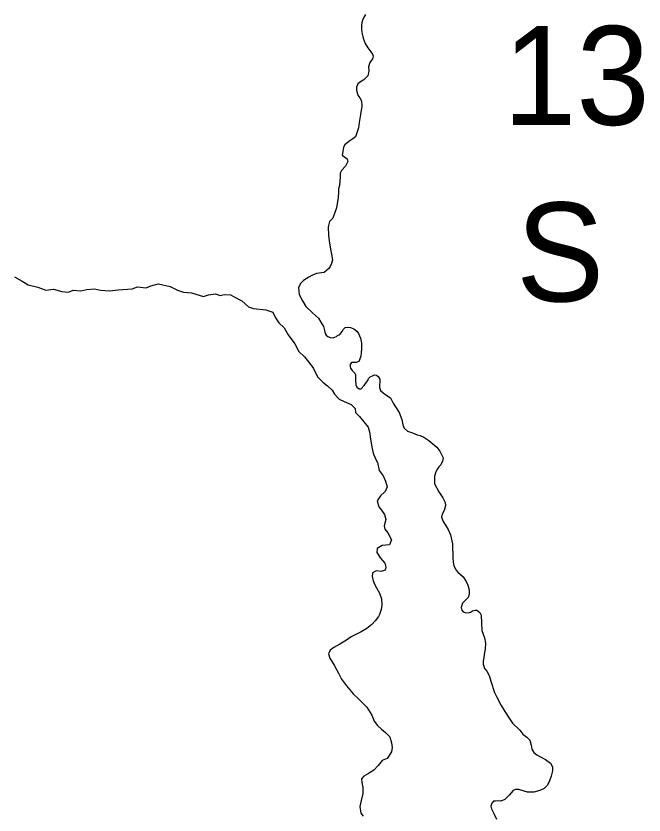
# Model space of a CAD drawing. Extents: x -492261 to -432772, y 1441225 to 1452922.
# Drawn here: x -459293.9 to -459176.4, y 1452357.2 to 1452506.5 of the extents above; entities that cross this region are included whole.
import ezdxf

# ---------------------------------------------------------------- set-up
doc = ezdxf.new("R2010")
doc.units = 0
doc.layers.add('Default', color=7, linetype='Continuous')

msp = doc.modelspace()

# ---------------------------------------------------------------- linework, layer by layer
at = {"layer": 'Default'}
for points in [[(-459228.54, 1452506.83), (-459228.89, 1452506.18), (-459229.12, 1452505.58), (-459229.26, 1452504.85), (-459229.26, 1452503.95), (-459229.14, 1452503.17), (-459228.99, 1452502.4), (-459228.56, 1452501.4), (-459228.11, 1452500.57), (-459227.51, 1452499.85), (-459227.23, 1452499.42), (-459227.08, 1452499.02), (-459227.23, 1452498.49), (-459227.71, 1452497.82), (-459227.98, 1452497.04), (-459227.9, 1452496.21), (-459228.1, 1452495.36), (-459228.87, 1452494.59), (-459229.47, 1452494.23), (-459229.94, 1452493.86), (-459230.24, 1452493.21), (-459230.22, 1452492.66), (-459229.99, 1452491.75), (-459229.59, 1452491.2), (-459229.29, 1452490.65), (-459229.21, 1452489.7), (-459229.46, 1452488.12)], [(-459228.54, 1452506.83), (-459228.89, 1452506.18), (-459229.12, 1452505.58), (-459229.26, 1452504.85), (-459229.26, 1452503.95), (-459229.14, 1452503.17), (-459228.99, 1452502.4), (-459228.56, 1452501.4), (-459228.11, 1452500.57), (-459227.51, 1452499.85), (-459227.23, 1452499.42), (-459227.08, 1452499.02), (-459227.23, 1452498.49), (-459227.71, 1452497.82), (-459227.98, 1452497.04), (-459227.9, 1452496.21), (-459228.1, 1452495.36), (-459228.87, 1452494.59), (-459229.47, 1452494.23), (-459229.94, 1452493.86), (-459230.24, 1452493.21), (-459230.22, 1452492.66), (-459229.99, 1452491.75), (-459229.59, 1452491.2), (-459229.29, 1452490.65), (-459229.21, 1452489.7), (-459229.46, 1452488.12)], [(-459229.46, 1452488.12), (-459229.71, 1452486.62), (-459229.83, 1452485.64), (-459230.08, 1452484.89), (-459230.4, 1452483.94), (-459230.87, 1452483.54), (-459231.62, 1452483.06), (-459232.37, 1452482.44), (-459232.62, 1452482.01), (-459232.69, 1452481.58), (-459232.86, 1452480.51), (-459231.94, 1452479.83), (-459231.81, 1452479.31), (-459232.24, 1452478.45), (-459233.03, 1452477.65), (-459233.26, 1452477.15), (-459233.26, 1452476.43), (-459233.38, 1452474.82), (-459233.58, 1452474.22), (-459233.6, 1452473.65), (-459233.65, 1452472.62), (-459233.97, 1452470.66), (-459234.66, 1452468.76), (-459235.24, 1452468.11), (-459235.51, 1452467.13), (-459235.43, 1452465.53), (-459235.26, 1452464.05), (-459235, 1452462.63), (-459234.88, 1452462.02), (-459234.7, 1452460.95), (-459234.87, 1452460.25), (-459235.12, 1452459.72), (-459235.4, 1452459.34), (-459236.24, 1452458.59), (-459237.71, 1452458.39), (-459238.59, 1452458.04), (-459239.14, 1452457.74), (-459240.13, 1452457.11), (-459240.7, 1452456.51), (-459241.08, 1452455.73), (-459240.95, 1452454.45), (-459240.28, 1452453.3), (-459239.67, 1452452.23), (-459238.45, 1452451.03), (-459237.3, 1452450.03), (-459236.85, 1452449.33), (-459236.38, 1452448.5), (-459236.17, 1452447.75), (-459236.07, 1452447.2), (-459235.87, 1452446.85), (-459235.55, 1452446.62), (-459235.12, 1452446.45), (-459234.6, 1452446.35), (-459233.98, 1452446.65), (-459233.75, 1452446.8), (-459233.3, 1452447), (-459232.91, 1452447.58), (-459232.63, 1452448), (-459232.36, 1452448.28), (-459231.84, 1452448.38), (-459231.34, 1452448.31), (-459230.71, 1452448.06), (-459230.14, 1452447.61), (-459229.81, 1452447.21), (-459229.49, 1452446.31), (-459229.29, 1452445.35), (-459229.28, 1452444.4), (-459229.33, 1452443.6), (-459229.43, 1452442.93), (-459229.63, 1452442.27), (-459229.8, 1452441.92), (-459230.28, 1452441.75), (-459230.68, 1452441.75), (-459231.15, 1452441.75), (-459231.37, 1452441.4), (-459231.4, 1452441.04), (-459231.32, 1452440.72), (-459231, 1452440.27), (-459230.7, 1452439.97), (-459230.5, 1452439.74), (-459230.4, 1452439.47), (-459230.37, 1452439.17), (-459230.37, 1452438.34), (-459230.35, 1452437.79), (-459230.34, 1452437.57), (-459230.17, 1452437.14), (-459229.72, 1452436.87), (-459229.32, 1452436.87), (-459228.75, 1452437.44), (-459228.35, 1452438.09), (-459228.1, 1452438.42), (-459227.95, 1452438.77), (-459227.63, 1452439.1), (-459227.08, 1452439.35), (-459226.86, 1452439.45), (-459226.48, 1452439.4), (-459226.13, 1452439.15), (-459225.83, 1452438.67), (-459225.86, 1452438.05), (-459225.88, 1452437.65), (-459225.9, 1452437.1)], [(-459229.46, 1452488.12), (-459229.71, 1452486.62), (-459229.83, 1452485.64), (-459230.08, 1452484.89), (-459230.4, 1452483.94), (-459230.87, 1452483.54), (-459231.62, 1452483.06), (-459232.37, 1452482.44), (-459232.62, 1452482.01), (-459232.69, 1452481.58), (-459232.86, 1452480.51), (-459231.94, 1452479.83), (-459231.81, 1452479.31), (-459232.24, 1452478.45), (-459233.03, 1452477.65), (-459233.26, 1452477.15), (-459233.26, 1452476.43), (-459233.38, 1452474.82), (-459233.58, 1452474.22), (-459233.6, 1452473.65), (-459233.65, 1452472.62), (-459233.97, 1452470.66), (-459234.66, 1452468.76), (-459235.24, 1452468.11), (-459235.51, 1452467.13), (-459235.43, 1452465.53), (-459235.26, 1452464.05), (-459235, 1452462.63), (-459234.88, 1452462.02), (-459234.7, 1452460.95), (-459234.87, 1452460.25), (-459235.12, 1452459.72), (-459235.4, 1452459.34), (-459236.24, 1452458.59), (-459237.71, 1452458.39), (-459238.59, 1452458.04), (-459239.14, 1452457.74), (-459240.13, 1452457.11), (-459240.7, 1452456.51), (-459241.08, 1452455.73), (-459240.95, 1452454.45), (-459240.28, 1452453.3), (-459239.67, 1452452.23), (-459238.45, 1452451.03), (-459237.3, 1452450.03), (-459236.85, 1452449.33), (-459236.38, 1452448.5), (-459236.17, 1452447.75), (-459236.07, 1452447.2), (-459235.87, 1452446.85), (-459235.55, 1452446.62), (-459235.12, 1452446.45), (-459234.6, 1452446.35), (-459233.98, 1452446.65), (-459233.75, 1452446.8), (-459233.3, 1452447), (-459232.91, 1452447.58), (-459232.63, 1452448), (-459232.36, 1452448.28), (-459231.84, 1452448.38), (-459231.34, 1452448.31), (-459230.71, 1452448.06), (-459230.14, 1452447.61), (-459229.81, 1452447.21), (-459229.49, 1452446.31), (-459229.29, 1452445.35), (-459229.28, 1452444.4), (-459229.33, 1452443.6), (-459229.43, 1452442.93), (-459229.63, 1452442.27), (-459229.8, 1452441.92), (-459230.28, 1452441.75), (-459230.68, 1452441.75), (-459231.15, 1452441.75), (-459231.37, 1452441.4), (-459231.4, 1452441.04), (-459231.32, 1452440.72), (-459231, 1452440.27), (-459230.7, 1452439.97), (-459230.5, 1452439.74), (-459230.4, 1452439.47), (-459230.37, 1452439.17), (-459230.37, 1452438.34), (-459230.35, 1452437.79), (-459230.34, 1452437.57), (-459230.17, 1452437.14), (-459229.72, 1452436.87), (-459229.32, 1452436.87), (-459228.75, 1452437.44), (-459228.35, 1452438.09), (-459228.1, 1452438.42), (-459227.95, 1452438.77), (-459227.63, 1452439.1), (-459227.08, 1452439.35), (-459226.86, 1452439.45), (-459226.48, 1452439.4), (-459226.13, 1452439.15), (-459225.83, 1452438.67), (-459225.86, 1452438.05), (-459225.88, 1452437.65), (-459225.9, 1452437.1)], [(-459294.16, 1452457.76), (-459292.7, 1452456.97), (-459291.59, 1452456.25), (-459289.78, 1452455.86), (-459288.27, 1452455.31), (-459286.84, 1452455.48), (-459285.28, 1452455.02), (-459284.07, 1452454.91), (-459283.17, 1452455.27), (-459281.77, 1452455.15), (-459280.64, 1452455.41), (-459279.22, 1452455.54), (-459278.1, 1452455.27), (-459276.4, 1452455.18), (-459274.75, 1452455.37), (-459272.17, 1452455.52), (-459271.18, 1452455.9), (-459269.55, 1452455.72), (-459268.66, 1452456.11), (-459267.21, 1452456.44), (-459265.05, 1452455.95), (-459263.68, 1452455.29), (-459262.55, 1452454.89), (-459261.07, 1452454.79), (-459258.83, 1452454.11), (-459257.91, 1452454.39), (-459256.56, 1452454.61), (-459255.71, 1452454.3), (-459254.98, 1452454.5), (-459253.79, 1452454.43), (-459253.09, 1452454.04), (-459251.68, 1452453.27), (-459250.38, 1452452.15), (-459249.5, 1452451.85), (-459247.15, 1452451.59), (-459245.88, 1452451.17), (-459245.38, 1452450.14), (-459244.74, 1452449.16), (-459243.73, 1452448.22), (-459243, 1452446.91), (-459241.75, 1452445.23), (-459240.97, 1452443.84), (-459239.95, 1452442.82), (-459238.96, 1452441.55), (-459238.26, 1452440.67), (-459237.49, 1452439.09), (-459236.48, 1452438.08), (-459235.64, 1452437.38), (-459234.76, 1452436.58), (-459234.35, 1452435.84), (-459233.46, 1452434.92)], [(-459225.9, 1452437.1), (-459225.75, 1452436.55), (-459225.25, 1452436.07), (-459224.55, 1452435.6), (-459223.85, 1452435.15), (-459223.35, 1452434.19), (-459222.23, 1452432.42), (-459221.75, 1452431.14), (-459221.55, 1452430.14), (-459221.3, 1452429.49), (-459220.65, 1452428.91), (-459219.73, 1452428.62), (-459218.88, 1452428.27), (-459218.28, 1452428.09), (-459217.63, 1452427.82), (-459216.68, 1452427.19), (-459215.21, 1452425.97), (-459214.63, 1452425.19), (-459214.33, 1452424.59), (-459214.03, 1452423.94), (-459214.11, 1452423.31), (-459214.45, 1452422.64), (-459214.8, 1452422.24), (-459215.05, 1452421.89), (-459215.35, 1452421.31), (-459215.6, 1452420.51), (-459215.62, 1452419.11), (-459214.82, 1452417.58), (-459214.04, 1452416.45), (-459213.62, 1452415.58), (-459213.57, 1452415.03), (-459213.84, 1452414.12), (-459214.19, 1452413.42), (-459214.29, 1452412.85), (-459213.99, 1452412.05), (-459213.54, 1452411.37), (-459213.09, 1452410.52), (-459212.61, 1452409.57), (-459212.23, 1452407.89), (-459212.18, 1452405.21), (-459212.13, 1452404.46), (-459211.98, 1452403.74), (-459211.58, 1452402.93), (-459211.25, 1452402.58), (-459210.28, 1452401.68), (-459209.73, 1452400.86), (-459209.4, 1452400.13), (-459209.23, 1452399.51), (-459209.12, 1452398.96), (-459209.15, 1452398.48), (-459209.32, 1452397.83), (-459209.75, 1452397.43), (-459210.09, 1452397.1), (-459210.37, 1452396.8), (-459210.64, 1452395.95), (-459210.52, 1452395.5), (-459210.24, 1452395.15), (-459209.89, 1452395.05), (-459209.34, 1452394.95), (-459208.92, 1452395.1), (-459208.52, 1452395.38), (-459208.02, 1452395.48), (-459207.72, 1452395.48), (-459207.17, 1452395.03), (-459206.87, 1452394.55), (-459206.79, 1452391.7), (-459206.27, 1452390.32), (-459206.09, 1452389.32), (-459206.14, 1452388.19), (-459206.29, 1452387.54), (-459206.43, 1452386.61), (-459206.53, 1452385.94), (-459206.51, 1452385.41), (-459206.43, 1452384.99), (-459206.26, 1452384.59), (-459205.81, 1452384.06), (-459205.43, 1452383.24), (-459205.1, 1452382.23), (-459204.38, 1452380.11), (-459204.03, 1452379.33), (-459203.15, 1452377.68), (-459202.48, 1452376.53), (-459201.57, 1452375.1), (-459201.02, 1452374.33), (-459199.68, 1452373.05), (-459199.08, 1452372.3), (-459198.38, 1452371.73), (-459197.8, 1452371.15), (-459197.55, 1452370.23), (-459197.4, 1452369.47), (-459197.05, 1452368.9), (-459196.52, 1452368.45), (-459195.9, 1452368.1), (-459194.85, 1452367.55), (-459193.95, 1452366.85), (-459193.58, 1452366.17), (-459193.55, 1452365.42), (-459193.8, 1452364.45), (-459194.12, 1452363.59), (-459194.49, 1452362.77), (-459195.14, 1452362.14)], [(-459225.9, 1452437.1), (-459225.75, 1452436.55), (-459225.25, 1452436.07), (-459224.55, 1452435.6), (-459223.85, 1452435.15), (-459223.35, 1452434.19), (-459222.23, 1452432.42), (-459221.75, 1452431.14), (-459221.55, 1452430.14), (-459221.3, 1452429.49), (-459220.65, 1452428.91), (-459219.73, 1452428.62), (-459218.88, 1452428.27), (-459218.28, 1452428.09), (-459217.63, 1452427.82), (-459216.68, 1452427.19), (-459215.21, 1452425.97), (-459214.63, 1452425.19), (-459214.33, 1452424.59), (-459214.03, 1452423.94), (-459214.11, 1452423.31), (-459214.45, 1452422.64), (-459214.8, 1452422.24), (-459215.05, 1452421.89), (-459215.35, 1452421.31), (-459215.6, 1452420.51), (-459215.62, 1452419.11), (-459214.82, 1452417.58), (-459214.04, 1452416.45), (-459213.62, 1452415.58), (-459213.57, 1452415.03), (-459213.84, 1452414.12), (-459214.19, 1452413.42), (-459214.29, 1452412.85), (-459213.99, 1452412.05), (-459213.54, 1452411.37), (-459213.09, 1452410.52), (-459212.61, 1452409.57), (-459212.23, 1452407.89), (-459212.18, 1452405.21), (-459212.13, 1452404.46), (-459211.98, 1452403.74), (-459211.58, 1452402.93), (-459211.25, 1452402.58), (-459210.28, 1452401.68), (-459209.73, 1452400.86), (-459209.4, 1452400.13), (-459209.23, 1452399.51), (-459209.12, 1452398.96), (-459209.15, 1452398.48), (-459209.32, 1452397.83), (-459209.75, 1452397.43), (-459210.09, 1452397.1), (-459210.37, 1452396.8), (-459210.64, 1452395.95), (-459210.52, 1452395.5), (-459210.24, 1452395.15), (-459209.89, 1452395.05), (-459209.34, 1452394.95), (-459208.92, 1452395.1), (-459208.52, 1452395.38), (-459208.02, 1452395.48), (-459207.72, 1452395.48), (-459207.17, 1452395.03), (-459206.87, 1452394.55), (-459206.79, 1452391.7), (-459206.27, 1452390.32), (-459206.09, 1452389.32), (-459206.14, 1452388.19), (-459206.29, 1452387.54), (-459206.43, 1452386.61), (-459206.53, 1452385.94), (-459206.51, 1452385.41), (-459206.43, 1452384.99), (-459206.26, 1452384.59), (-459205.81, 1452384.06), (-459205.43, 1452383.24), (-459205.1, 1452382.23), (-459204.38, 1452380.11), (-459204.03, 1452379.33), (-459203.15, 1452377.68), (-459202.48, 1452376.53), (-459201.57, 1452375.1), (-459201.02, 1452374.33), (-459199.68, 1452373.05), (-459199.08, 1452372.3), (-459198.38, 1452371.73), (-459197.8, 1452371.15), (-459197.55, 1452370.23), (-459197.4, 1452369.47), (-459197.05, 1452368.9), (-459196.52, 1452368.45), (-459195.9, 1452368.1), (-459194.85, 1452367.55), (-459193.95, 1452366.85), (-459193.58, 1452366.17), (-459193.55, 1452365.42), (-459193.8, 1452364.45), (-459194.12, 1452363.59), (-459194.49, 1452362.77), (-459195.14, 1452362.14)], [(-459233.46, 1452434.92), (-459232.49, 1452434.48), (-459231.21, 1452433.93), (-459230.43, 1452433.15), (-459230.37, 1452432.43), (-459229.68, 1452431.69), (-459228.81, 1452430.7), (-459228.03, 1452429.66), (-459227.8, 1452428.81), (-459227.61, 1452427.41), (-459227.34, 1452426), (-459227.09, 1452424.79), (-459226.68, 1452423.73), (-459226.31, 1452423.07), (-459225.96, 1452421.56), (-459225.21, 1452420.57), (-459224.76, 1452419.57), (-459224.45, 1452418.5), (-459224.83, 1452417.63), (-459225.74, 1452416.86), (-459226.32, 1452415.91), (-459226.02, 1452414.76), (-459225.53, 1452414.18), (-459224.97, 1452413.36), (-459224.71, 1452412.43), (-459225.01, 1452411.22), (-459224.92, 1452410.63), (-459224.37, 1452409.92), (-459223.66, 1452408.59), (-459224.03, 1452407.68), (-459225.43, 1452407.53), (-459226.36, 1452407.02), (-459226.42, 1452406.28), (-459225.7, 1452405.18), (-459224.94, 1452404.27), (-459224.75, 1452403.54), (-459224.88, 1452402.97), (-459225.58, 1452402.68), (-459226.56, 1452402.84), (-459227.21, 1452402.44), (-459227.29, 1452401.78), (-459227.1, 1452400.96), (-459226.75, 1452400.09)], [(-459226.75, 1452400.09), (-459225.9, 1452398.64), (-459225.56, 1452397.57), (-459225.5, 1452396.43), (-459225.61, 1452395.61), (-459225.93, 1452394.67), (-459226.12, 1452394.27), (-459226.7, 1452393.5), (-459227.34, 1452392.82), (-459228.26, 1452392.04), (-459229.34, 1452391.44), (-459230.48, 1452390.88), (-459231.22, 1452390.5), (-459232.06, 1452389.86), (-459233.34, 1452389.11), (-459234.46, 1452388.5), (-459235.15, 1452387.99), (-459235.45, 1452387.33), (-459235.18, 1452386.51), (-459234.36, 1452385.21), (-459233.58, 1452383.69), (-459233, 1452382.57), (-459232.05, 1452381.36), (-459230.84, 1452379.81), (-459229.77, 1452378.81), (-459228.29, 1452377.32), (-459227.32, 1452375.87), (-459226.92, 1452374.73), (-459226.26, 1452373.9), (-459225.56, 1452373.21), (-459224.79, 1452372.64), (-459224, 1452371.78), (-459223.66, 1452370.68), (-459223.57, 1452369.81), (-459223.67, 1452368.98), (-459224.49, 1452367.75), (-459225.42, 1452367.35), (-459226.15, 1452366.44), (-459226.95, 1452365.56), (-459227.98, 1452364.95), (-459228.82, 1452364.42), (-459229.26, 1452363.93), (-459229.2, 1452363.27), (-459229, 1452362.34), (-459229, 1452361.21), (-459229.32, 1452359.89), (-459229.57, 1452358.76), (-459229.4, 1452357.55), (-459228.98, 1452356.95)], [(-459195.14, 1452362.14), (-459195.91, 1452361.74), (-459197.06, 1452361.46), (-459198.23, 1452361.48), (-459199.68, 1452361.88), (-459199.88, 1452361.93), (-459200.48, 1452361.98), (-459200.9, 1452361.76), (-459201.67, 1452360.9), (-459202.5, 1452360.08), (-459203.22, 1452359.8), (-459203.64, 1452359.82), (-459204.22, 1452359.8), (-459204.59, 1452359.77), (-459204.91, 1452359.4), (-459205.09, 1452358.87), (-459204.99, 1452358.37), (-459204.46, 1452357.37), (-459204.06, 1452356.44)], [(-459195.14, 1452362.14), (-459195.91, 1452361.74), (-459197.06, 1452361.46), (-459198.23, 1452361.48), (-459199.68, 1452361.88), (-459199.88, 1452361.93), (-459200.48, 1452361.98), (-459200.9, 1452361.76), (-459201.67, 1452360.9), (-459202.5, 1452360.08), (-459203.22, 1452359.8), (-459203.64, 1452359.82), (-459204.22, 1452359.8), (-459204.59, 1452359.77), (-459204.91, 1452359.4), (-459205.09, 1452358.87), (-459204.99, 1452358.37), (-459204.46, 1452357.37), (-459204.06, 1452356.44)]]:
    msp.add_lwpolyline(points, dxfattribs=at)

# ---------------------------------------------------------------- texts
for s, p in [('13', (-459202.85, 1452486.18)), ('S', (-459200.37, 1452453.18))]:
    msp.add_text(s, height=18.48, dxfattribs=at).set_placement(p)

doc.saveas('drawing.dxf')
